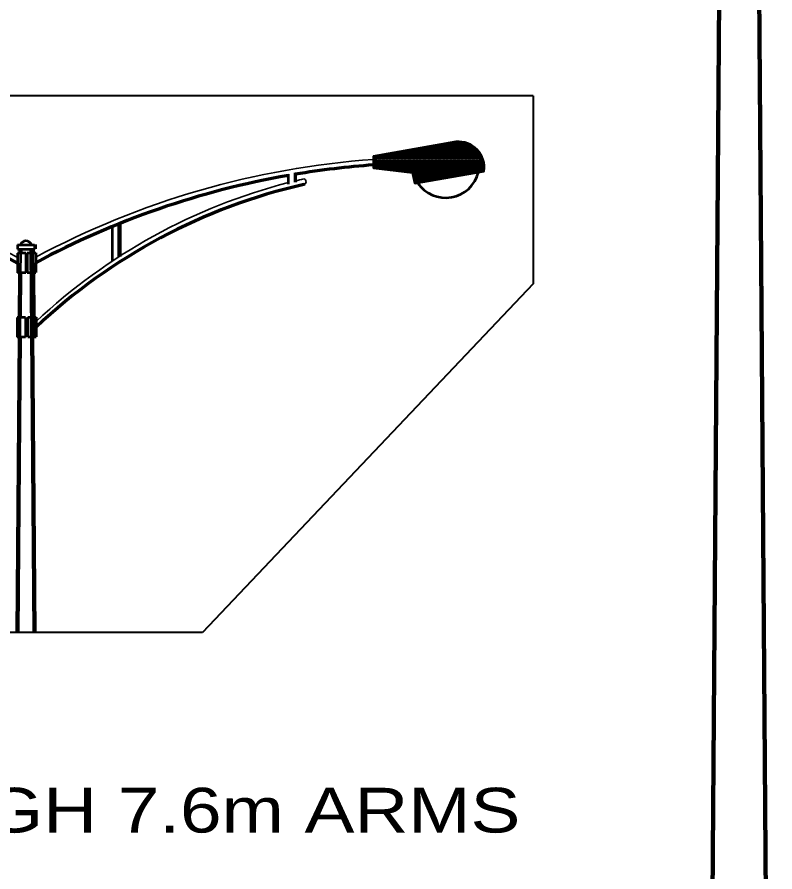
# Model space of a CAD drawing. Extents: x -32 to 824, y -12 to 532.
# Drawn here: x 116.9 to 167.8, y 394.1 to 451.4 of the extents above; entities that cross this region are included whole.
import ezdxf

# ---------------------------------------------------------------- set-up
doc = ezdxf.new("R2010")
doc.units = 0
doc.header["$LTSCALE"] = 1.2
doc.layers.add('1', color=7, linetype='Continuous', lineweight=13)

msp = doc.modelspace()

# ---------------------------------------------------------------- linework, layer by layer
at = {"layer": '1', "lineweight": 90}
for p, q in [((167.802, 313.221), (166.602, 471.621)), ((164.059, 452.721), (163.002, 313.221)), ((123.793, 435.35), (123.793, 437.553)), ((117.981, 435.866), (117.983, 435.585)), ((117.144, 435.848), (117.142, 435.567)), ((118.089, 410.12), (117.894, 435.848)), ((117.132, 434.254), (117.109, 431.254)), ((117.993, 434.273), (118.015, 431.273)), ((117.099, 429.942), (116.949, 410.12))]:
    msp.add_line(p, q, dxfattribs=at)
at = {"layer": '1', "lineweight": 40}
for p, q in [((151.561, 446.121), (83.161, 446.121)), ((151.561, 446.121), (151.561, 433.521)), ((151.561, 433.521), (129.361, 410.12)), ((129.361, 410.12), (105.361, 410.12))]:
    msp.add_line(p, q, dxfattribs=at)
at = {"layer": '1', "lineweight": 53}
for p, q in [((145.539, 441.913), (144.718, 442.735)), ((145.592, 441.913), (144.763, 442.743)), ((145.645, 441.913), (144.808, 442.751)), ((145.698, 441.913), (144.853, 442.759)), ((145.751, 441.913), (144.898, 442.767)), ((145.804, 441.913), (144.943, 442.775)), ((145.857, 441.913), (144.988, 442.783)), ((145.91, 441.913), (145.033, 442.791)), ((145.963, 441.913), (145.078, 442.799)), ((146.017, 441.913), (145.123, 442.806)), ((146.07, 441.913), (145.168, 442.814)), ((146.123, 441.913), (145.214, 442.822)), ((146.175, 441.913), (145.258, 442.83)), ((146.229, 441.913), (145.304, 442.838)), ((146.282, 441.913), (145.349, 442.846)), ((146.335, 441.913), (145.394, 442.854)), ((146.388, 441.913), (145.439, 442.862)), ((146.441, 441.913), (145.484, 442.87)), ((146.494, 441.913), (145.529, 442.878)), ((146.547, 441.913), (145.574, 442.886)), ((146.6, 441.913), (145.619, 442.894)), ((146.653, 441.913), (145.664, 442.902)), ((146.706, 441.913), (145.709, 442.91)), ((146.759, 441.913), (145.755, 442.918)), ((146.812, 441.913), (145.799, 442.926)), ((146.865, 441.913), (145.845, 442.934)), ((146.918, 441.913), (145.89, 442.942)), ((146.971, 441.913), (145.935, 442.95)), ((147.024, 441.913), (145.98, 442.958)), ((147.077, 441.913), (146.025, 442.965)), ((147.13, 441.913), (146.07, 442.973)), ((147.183, 441.913), (146.115, 442.981)), ((147.236, 441.913), (146.16, 442.989)), ((147.289, 441.913), (146.205, 442.997)), ((147.342, 441.913), (146.25, 443.005)), ((147.395, 441.913), (146.296, 443.013)), ((147.448, 441.913), (146.341, 443.021)), ((147.501, 441.913), (146.386, 443.029)), ((147.554, 441.913), (146.434, 443.034)), ((147.608, 441.913), (146.484, 443.036)), ((147.661, 441.913), (146.537, 443.037)), ((147.714, 441.913), (146.59, 443.037)), ((147.767, 441.913), (146.642, 443.038)), ((147.82, 441.913), (146.701, 443.032)), ((147.873, 441.913), (146.759, 443.026)), ((147.926, 441.913), (146.818, 443.021)), ((147.979, 441.913), (146.885, 443.007)), ((148.235, 441.71), (146.951, 442.994)), ((148.22, 441.778), (147.021, 442.977)), ((148.194, 441.857), (147.099, 442.953)), ((148.167, 441.937), (147.178, 442.926)), ((148.127, 442.03), (147.272, 442.886)), ((148.079, 442.131), (147.376, 442.834)), ((148.003, 442.261), (147.503, 442.76)), ((141.721, 441.913), (141.472, 442.163)), ((141.774, 441.913), (141.517, 442.171)), ((141.827, 441.913), (141.562, 442.178)), ((141.88, 441.913), (141.607, 442.186)), ((141.933, 441.913), (141.652, 442.194)), ((141.986, 441.913), (141.697, 442.202)), ((142.039, 441.913), (141.742, 442.21)), ((142.092, 441.913), (141.787, 442.218)), ((142.145, 441.913), (141.832, 442.226)), ((142.198, 441.913), (141.877, 442.234)), ((142.251, 441.913), (141.922, 442.242)), ((142.304, 441.913), (141.968, 442.25)), ((142.357, 441.913), (142.013, 442.258)), ((142.41, 441.913), (142.058, 442.266)), ((142.463, 441.913), (142.103, 442.274)), ((142.516, 441.913), (142.148, 442.282)), ((142.569, 441.913), (142.193, 442.29)), ((142.622, 441.913), (142.238, 442.298)), ((142.675, 441.913), (142.283, 442.306)), ((142.728, 441.913), (142.328, 442.314)), ((142.781, 441.913), (142.373, 442.322)), ((142.835, 441.913), (142.418, 442.329)), ((142.888, 441.913), (142.463, 442.337)), ((142.941, 441.913), (142.508, 442.345)), ((142.994, 441.913), (142.554, 442.353)), ((143.047, 441.913), (142.599, 442.361)), ((143.1, 441.913), (142.644, 442.369)), ((143.153, 441.913), (142.689, 442.377)), ((143.206, 441.913), (142.734, 442.385)), ((143.259, 441.913), (142.779, 442.393)), ((143.312, 441.913), (142.824, 442.401)), ((143.365, 441.913), (142.869, 442.409)), ((143.418, 441.913), (142.914, 442.417)), ((143.471, 441.913), (142.959, 442.425)), ((143.524, 441.913), (143.004, 442.433)), ((143.577, 441.913), (143.049, 442.441)), ((143.63, 441.913), (143.095, 442.449)), ((143.683, 441.913), (143.14, 442.457)), ((143.736, 441.913), (143.185, 442.465)), ((143.789, 441.913), (143.23, 442.473)), ((143.842, 441.913), (143.275, 442.481)), ((143.895, 441.913), (143.32, 442.489)), ((143.948, 441.913), (143.365, 442.496)), ((144.001, 441.913), (143.41, 442.504)), ((144.054, 441.913), (143.455, 442.512)), ((144.107, 441.913), (143.5, 442.52)), ((144.16, 441.913), (143.545, 442.528)), ((144.213, 441.913), (143.591, 442.536)), ((144.266, 441.913), (143.636, 442.544)), ((144.319, 441.913), (143.681, 442.552)), ((144.372, 441.913), (143.726, 442.56)), ((144.425, 441.913), (143.771, 442.568)), ((144.478, 441.913), (143.816, 442.576)), ((144.531, 441.913), (143.861, 442.584)), ((144.585, 441.913), (143.906, 442.592)), ((144.638, 441.913), (143.951, 442.6)), ((144.691, 441.913), (143.996, 442.608)), ((144.744, 441.913), (144.041, 442.616)), ((144.797, 441.913), (144.086, 442.624)), ((144.85, 441.913), (144.132, 442.632)), ((144.903, 441.913), (144.177, 442.639)), ((144.956, 441.913), (144.222, 442.648)), ((145.009, 441.913), (144.267, 442.655)), ((145.062, 441.913), (144.312, 442.663)), ((145.115, 441.913), (144.357, 442.671)), ((145.168, 441.913), (144.402, 442.679)), ((145.221, 441.913), (144.447, 442.687)), ((145.274, 441.913), (144.492, 442.695)), ((145.327, 441.913), (144.537, 442.703)), ((145.38, 441.913), (144.582, 442.711)), ((145.433, 441.913), (144.627, 442.719)), ((145.486, 441.913), (144.673, 442.727)), ((147.767, 442.549), (147.765, 442.551)), ((141.043, 441.849), (140.856, 442.036)), ((141.63, 441.209), (140.856, 441.983)), ((141.569, 441.216), (140.856, 441.93)), ((141.509, 441.224), (140.856, 441.877)), ((141.448, 441.231), (140.856, 441.824)), ((141.388, 441.239), (140.856, 441.771)), ((141.328, 441.246), (140.856, 441.718)), ((141.267, 441.253), (140.856, 441.665)), ((141.207, 441.261), (140.856, 441.612)), ((141.043, 441.902), (140.886, 442.059)), ((141.084, 441.913), (140.93, 442.067)), ((141.137, 441.913), (140.976, 442.075)), ((141.191, 441.913), (141.021, 442.083)), ((141.244, 441.913), (141.066, 442.091)), ((141.69, 441.201), (141.072, 441.82)), ((141.297, 441.913), (141.111, 442.099)), ((141.751, 441.194), (141.125, 441.82)), ((141.35, 441.913), (141.156, 442.107)), ((141.811, 441.187), (141.178, 441.82)), ((141.403, 441.913), (141.201, 442.115)), ((141.871, 441.179), (141.231, 441.82)), ((141.456, 441.913), (141.246, 442.123)), ((141.932, 441.172), (141.284, 441.82)), ((141.509, 441.913), (141.291, 442.131)), ((141.562, 441.913), (141.336, 442.139)), ((141.993, 441.164), (141.337, 441.82)), ((141.615, 441.913), (141.381, 442.147)), ((142.053, 441.157), (141.39, 441.82)), ((141.668, 441.913), (141.427, 442.155)), ((142.113, 441.15), (141.443, 441.82)), ((142.174, 441.142), (141.496, 441.82)), ((142.234, 441.135), (141.549, 441.82)), ((142.295, 441.127), (141.602, 441.82)), ((142.355, 441.12), (141.655, 441.82)), ((142.416, 441.112), (141.709, 441.82)), ((142.476, 441.105), (141.762, 441.82)), ((142.537, 441.098), (141.815, 441.82)), ((142.597, 441.09), (141.868, 441.82)), ((142.657, 441.083), (141.921, 441.82)), ((142.718, 441.075), (141.974, 441.82)), ((142.778, 441.068), (142.027, 441.82)), ((142.839, 441.06), (142.08, 441.82)), ((142.899, 441.053), (142.133, 441.82)), ((142.96, 441.046), (142.186, 441.82)), ((143.02, 441.038), (142.239, 441.82)), ((143.081, 441.031), (142.292, 441.82)), ((143.141, 441.023), (142.345, 441.82)), ((143.202, 441.016), (142.398, 441.82)), ((143.262, 441.008), (142.451, 441.82)), ((143.323, 441.001), (142.504, 441.82)), ((143.383, 440.994), (142.557, 441.82)), ((143.443, 440.986), (142.61, 441.82)), ((144.135, 440.347), (142.663, 441.82)), ((144.18, 440.355), (142.716, 441.82)), ((144.225, 440.363), (142.769, 441.82)), ((144.27, 440.371), (142.822, 441.82)), ((144.316, 440.379), (142.875, 441.82)), ((144.361, 440.387), (142.928, 441.82)), ((144.406, 440.395), (142.981, 441.82)), ((144.451, 440.403), (143.034, 441.82)), ((144.496, 440.411), (143.087, 441.82)), ((144.541, 440.419), (143.14, 441.82)), ((144.586, 440.427), (143.193, 441.82)), ((144.631, 440.435), (143.246, 441.82)), ((144.676, 440.443), (143.299, 441.82)), ((144.721, 440.451), (143.353, 441.82)), ((144.766, 440.459), (143.406, 441.82)), ((144.811, 440.467), (143.459, 441.82)), ((144.857, 440.475), (143.512, 441.82)), ((144.901, 440.483), (143.565, 441.82)), ((144.947, 440.49), (143.618, 441.82)), ((144.992, 440.499), (143.671, 441.82)), ((145.037, 440.506), (143.724, 441.82)), ((145.082, 440.514), (143.777, 441.82)), ((145.127, 440.522), (143.83, 441.82)), ((145.172, 440.53), (143.883, 441.82)), ((145.217, 440.538), (143.936, 441.82)), ((145.262, 440.546), (143.989, 441.82)), ((145.307, 440.554), (144.042, 441.82)), ((145.352, 440.562), (144.095, 441.82)), ((145.398, 440.57), (144.148, 441.82)), ((145.442, 440.578), (144.201, 441.82)), ((145.488, 440.586), (144.254, 441.82)), ((145.533, 440.594), (144.307, 441.82)), ((145.578, 440.602), (144.36, 441.82)), ((145.623, 440.61), (144.413, 441.82)), ((145.668, 440.618), (144.466, 441.82)), ((145.713, 440.626), (144.519, 441.82)), ((145.758, 440.634), (144.572, 441.82)), ((145.803, 440.642), (144.625, 441.82)), ((145.848, 440.65), (144.678, 441.82)), ((145.893, 440.658), (144.731, 441.82)), ((145.939, 440.665), (144.784, 441.82)), ((145.984, 440.673), (144.837, 441.82)), ((146.029, 440.681), (144.891, 441.82)), ((146.074, 440.689), (144.944, 441.82)), ((146.119, 440.697), (144.996, 441.82)), ((146.164, 440.705), (145.049, 441.82)), ((146.209, 440.713), (145.103, 441.82)), ((146.254, 440.721), (145.156, 441.82)), ((146.299, 440.729), (145.209, 441.82)), ((146.344, 440.737), (145.262, 441.82)), ((146.389, 440.745), (145.315, 441.82)), ((146.434, 440.753), (145.368, 441.82)), ((146.48, 440.761), (145.421, 441.82)), ((146.525, 440.769), (145.474, 441.82)), ((146.57, 440.777), (145.527, 441.82)), ((146.615, 440.785), (145.58, 441.82)), ((146.66, 440.793), (145.633, 441.82)), ((146.705, 440.801), (145.686, 441.82)), ((146.75, 440.809), (145.739, 441.82)), ((146.795, 440.817), (145.792, 441.82)), ((146.84, 440.824), (145.845, 441.82)), ((146.885, 440.832), (145.898, 441.82)), ((146.93, 440.84), (145.951, 441.82)), ((146.975, 440.848), (146.004, 441.82)), ((147.02, 440.856), (146.057, 441.82)), ((147.066, 440.864), (146.11, 441.82)), ((147.111, 440.872), (146.163, 441.82)), ((147.156, 440.88), (146.216, 441.82)), ((147.201, 440.888), (146.269, 441.82)), ((147.246, 440.896), (146.322, 441.82)), ((147.291, 440.904), (146.375, 441.82)), ((147.336, 440.912), (146.428, 441.82)), ((147.381, 440.92), (146.481, 441.82)), ((147.426, 440.928), (146.535, 441.82)), ((147.471, 440.936), (146.588, 441.82)), ((147.516, 440.944), (146.641, 441.82)), ((147.561, 440.952), (146.694, 441.82)), ((147.607, 440.96), (146.747, 441.82)), ((147.652, 440.968), (146.8, 441.82)), ((147.697, 440.976), (146.853, 441.82)), ((147.742, 440.983), (146.906, 441.82)), ((147.787, 440.991), (146.959, 441.82)), ((147.832, 440.999), (147.012, 441.82)), ((147.877, 441.007), (147.065, 441.82)), ((147.922, 441.015), (147.118, 441.82)), ((147.967, 441.023), (147.171, 441.82)), ((148.012, 441.031), (147.224, 441.82)), ((148.057, 441.039), (147.277, 441.82)), ((148.103, 441.047), (147.33, 441.82)), ((148.148, 441.055), (147.383, 441.82)), ((148.193, 441.063), (147.436, 441.82)), ((148.238, 441.071), (147.489, 441.82)), ((148.265, 441.097), (147.542, 441.82)), ((148.269, 441.145), (147.595, 441.82)), ((148.274, 441.194), (147.648, 441.82)), ((148.279, 441.242), (147.701, 441.82)), ((148.279, 441.294), (147.754, 441.82)), ((148.279, 441.348), (147.807, 441.82)), ((148.278, 441.402), (147.86, 441.82)), ((148.275, 441.458), (147.913, 441.82)), ((148.268, 441.518), (147.966, 441.82)), ((148.25, 441.642), (147.99, 441.902)), ((148.261, 441.578), (147.99, 441.849)), ((141.146, 441.268), (140.856, 441.559)), ((141.086, 441.276), (140.856, 441.506)), ((141.025, 441.283), (140.856, 441.453)), ((140.965, 441.291), (140.856, 441.4)), ((140.904, 441.298), (140.856, 441.347)), ((135.137, 440.209), (135.137, 440.88)), ((144.09, 440.34), (143.466, 440.964)), ((144.045, 440.332), (143.482, 440.895)), ((144, 440.324), (143.497, 440.826)), ((143.955, 440.316), (143.513, 440.757)), ((143.91, 440.308), (143.529, 440.688)), ((143.865, 440.3), (143.545, 440.619)), ((143.82, 440.292), (143.561, 440.55)), ((143.775, 440.284), (143.577, 440.481)), ((143.729, 440.276), (143.593, 440.412)), ((143.684, 440.268), (143.609, 440.343)), ((143.639, 440.26), (143.625, 440.275)), ((123.324, 435.044), (123.324, 437.362)), ((116.956, 436.129), (118.081, 436.129)), ((116.956, 436.129), (116.956, 435.848)), ((118.081, 436.129), (118.081, 435.848)), ((118.168, 436.148), (118.168, 435.866)), ((117.517, 435.567), (116.954, 435.567)), ((116.954, 435.567), (116.954, 434.254)), ((116.956, 435.848), (118.081, 435.848)), ((117.142, 435.567), (117.132, 434.254)), ((117.517, 435.567), (117.517, 434.254)), ((117.608, 435.585), (118.17, 435.585)), ((117.608, 435.585), (117.608, 434.273)), ((117.983, 435.585), (117.993, 434.273)), ((118.17, 435.585), (118.17, 434.273)), ((117.517, 434.254), (116.954, 434.254)), ((117.608, 434.273), (118.17, 434.273)), ((117.64, 431.273), (118.203, 431.273)), ((117.64, 431.273), (117.64, 429.96)), ((118.015, 431.273), (118.025, 429.96)), ((118.203, 431.273), (118.203, 429.96)), ((117.484, 431.254), (116.922, 431.254)), ((116.922, 431.254), (116.922, 429.942)), ((117.109, 431.254), (117.099, 429.942)), ((117.484, 431.254), (117.484, 429.942)), ((117.484, 429.942), (116.922, 429.942)), ((117.64, 429.96), (118.203, 429.96))]:
    msp.add_line(p, q, dxfattribs=at)
at = {"layer": '1', "lineweight": 70}
msp.add_line((135.606, 440.327), (135.606, 440.961), dxfattribs=at)
at = {"layer": '1', "lineweight": 53}
msp.add_lwpolyline([(146.395, 443.031), (140.856, 442.054), (140.856, 441.304), (143.461, 440.984), (143.629, 440.258), (148.263, 441.075), (148.263, 441.075)], dxfattribs=at)
at = {"layer": '1'}
msp.add_lwpolyline([(147.99, 441.913), (141.043, 441.913), (141.043, 441.82), (147.99, 441.82)], close=True, dxfattribs=at)
at = {"layer": '1', "lineweight": 53}
for centre, radius, start, end in [((146.567, 441.325), 1.714, 351.61838, 95.76047), ((145.694, 441.556), 2.267, 213.94941, 346.05238), ((136.081, 440.49), 0.323, 285.61712, 304.46983), ((117.519, 435.991), 0.398, 20.3922, 159.6078)]:
    msp.add_arc(centre, radius, start, end, dxfattribs=at)
at = {"layer": '1', "lineweight": 35}
for centre, radius, start, end in [((90.203, 385.303), 56.691, 61.84402, 85.88743), ((144.921, 385.321), 56.691, 94.11257, 118.15598), ((144.862, 402.564), 38.972, 102.88988, 103.7397), ((136.137, 440.366), 0.19, 279.37484, 80.62516), ((144.862, 402.564), 38.972, 104.45024, 133.16103)]:
    msp.add_arc(centre, radius, start, end, dxfattribs=at)
at = {"layer": '1', "lineweight": 70}
for centre, radius, start, end in [((144.921, 384.946), 56.691, 94.11257, 99.45792), ((90.203, 384.928), 56.691, 61.84402, 80.06146), ((144.921, 384.946), 56.691, 99.93854, 118.15598), ((144.862, 402.189), 38.972, 102.88988, 133.16103)]:
    msp.add_arc(centre, radius, start, end, dxfattribs=at)

# ---------------------------------------------------------------- texts
at = {"layer": '1', "width": 1.25}
msp.add_text('2.4m THROUGH 7.6m ARMS', height=3, dxfattribs=at).set_placement((84.398, 396.702))

doc.saveas('drawing.dxf')
